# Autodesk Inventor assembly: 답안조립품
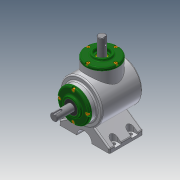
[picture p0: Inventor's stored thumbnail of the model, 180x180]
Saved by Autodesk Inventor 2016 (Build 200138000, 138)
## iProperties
Created: 2017-04
Part Number: 답안조립품
Document SubType Name: Assembly
Designer: Administrator
Author: Administrator
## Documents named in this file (14)
- D:\470407V1010\답안조립품.iam
- D:\470407V1010\본체.ipt
- D:\470407V1010\메인 축.ipt
- 메인 축.ipt
- D:\470407V1010\베어링 6203.ipt
- D:\470407V1010\커버.ipt
- D:\470407V1010\오일실 17 32 8.ipt
- D:\470407V1010\키 5x5.ipt
- D:\470407V1010\메인 베벨기어.ipt
- D:\470407V1010\볼트 M4.ipt
- D:\470407V1010\서브 축.ipt
- 서브 축.ipt
- D:\470407V1010\서브 베벨기어.ipt
- D:\470407V1010\키 4x4.ipt
